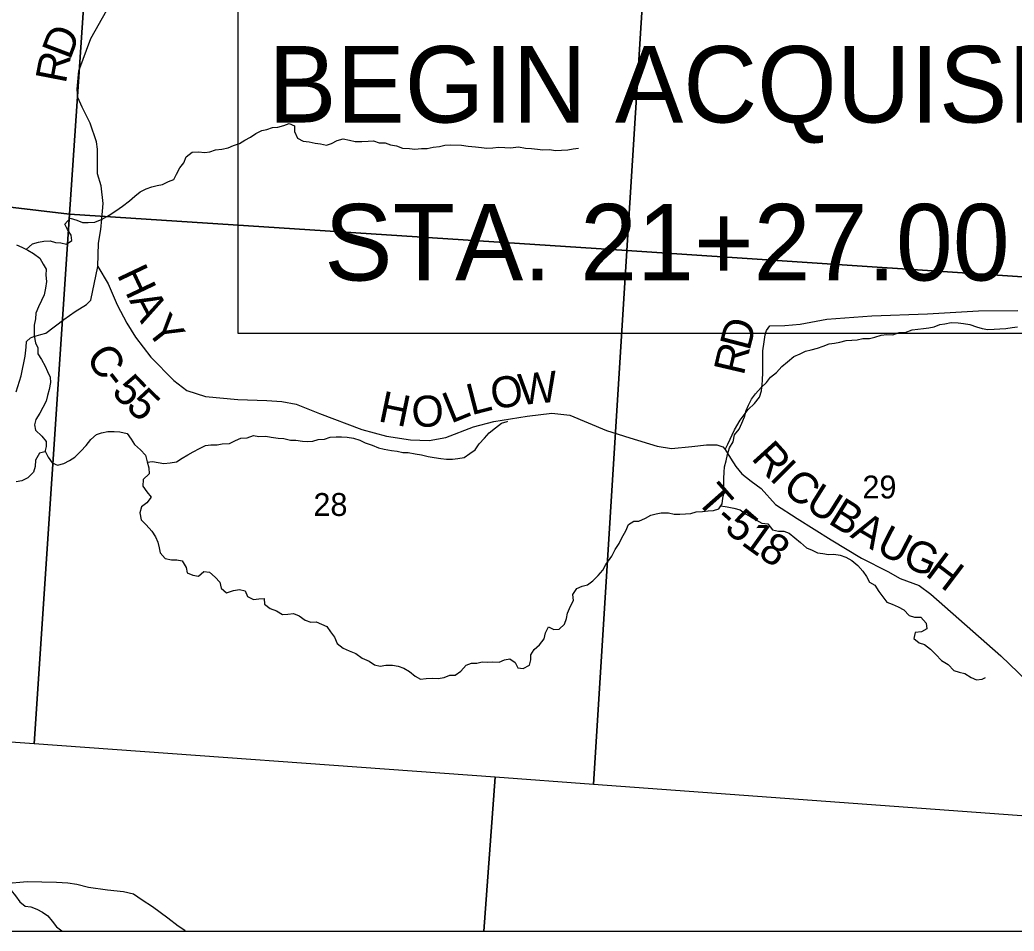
# Model space of a CAD drawing. Extents: x 5.6 to 39.6, y 0.7 to 22.7.
# Drawn here: x 11.039 to 12.858, y 14.907 to 16.574 of the extents above; entities that cross this region are included whole.
import ezdxf

# ---------------------------------------------------------------- set-up
doc = ezdxf.new("R2010")
doc.units = 0
doc.layers.add('Default', color=7, linetype='Continuous')
doc.layers.add('SH_Data', color=7, linetype='Continuous')

msp = doc.modelspace()

# ---------------------------------------------------------------- linework, layer by layer
at = {"layer": 'Default'}
for p, q in [((10.8627, 14.9074), (11.8881, 14.9074)), ((11.8881, 14.9074), (12.9445, 14.9074))]:
    msp.add_line(p, q, dxfattribs=at)
for points in [[(8.2518, 18.5322), (8.2518, 14.9074), (15.0518, 14.9074), (15.0518, 18.0251)], [(8.2518, 18.5322), (8.2518, 14.9074), (15.0518, 14.9074), (15.0518, 18.0251)], [(8.2518, 18.5322), (8.2518, 14.9074), (15.0518, 14.9074), (15.0518, 18.0251)], [(11.1813, 16.1232), (11.1813, 16.1232), (11.1827, 16.1657), (11.187, 16.1911), (11.189, 16.2105), (11.1914, 16.2382), (11.1875, 16.2708), (11.1812, 16.2925), (11.1812, 16.3073), (11.1807, 16.3377), (11.1792, 16.351), (11.1673, 16.3856), (11.1527, 16.4149), (11.1449, 16.4324), (11.1438, 16.4476), (11.147, 16.4813), (11.169, 16.5404), (11.2275, 16.6448)], [(11.0505, 16.1544), (11.0618, 16.1649), (11.0732, 16.1677), (11.0827, 16.1693), (11.0941, 16.1699), (11.1039, 16.1674), (11.1141, 16.1664), (11.1242, 16.1643), (11.1339, 16.1705), (11.1326, 16.1808), (11.126, 16.1911), (11.1213, 16.2007), (11.131, 16.2119), (11.1434, 16.2078), (11.1535, 16.2038), (11.1641, 16.2036), (11.1759, 16.2044), (11.1893, 16.2095), (11.2023, 16.2171), (11.2146, 16.2252), (11.2265, 16.2333), (11.2393, 16.2432), (11.2493, 16.2517), (11.2589, 16.2595), (11.2701, 16.2653), (11.2807, 16.2689), (11.2903, 16.2713), (11.2998, 16.2734), (11.3109, 16.2784), (11.3204, 16.2824), (11.3256, 16.2922), (11.3315, 16.3034), (11.3389, 16.3131), (11.3433, 16.3236), (11.3541, 16.3321), (11.3655, 16.333), (11.3772, 16.332), (11.3867, 16.3329), (11.397, 16.3365), (11.4084, 16.3381), (11.4198, 16.3401), (11.4301, 16.3444), (11.4408, 16.348), (11.4504, 16.3542), (11.4612, 16.3597), (11.4708, 16.3667), (11.4815, 16.3721), (11.491, 16.3738), (11.5009, 16.3774), (11.5112, 16.3783), (11.5222, 16.3811), (11.5318, 16.385), (11.5415, 16.3807), (11.5417, 16.3704), (11.5467, 16.3582), (11.5572, 16.3522), (11.5685, 16.3512), (11.5791, 16.3487), (11.5889, 16.3474), (11.5998, 16.3452), (11.6094, 16.3484), (11.6193, 16.3539), (11.6308, 16.3567), (11.6424, 16.3541), (11.6526, 16.3516), (11.6647, 16.3521), (11.6761, 16.3526), (11.6863, 16.3532), (11.6961, 16.3495), (11.7071, 16.3493), (11.7172, 16.3457), (11.7282, 16.3439), (11.7391, 16.3399), (11.7516, 16.3392), (11.7614, 16.3378), (11.7739, 16.3391), (11.7841, 16.3389), (11.7955, 16.3413), (11.8069, 16.3429), (11.8165, 16.345), (11.8267, 16.3455), (11.8471, 16.345), (11.8592, 16.3436), (11.8724, 16.3418), (11.8834, 16.3408), (11.8936, 16.3398), (11.9042, 16.3404), (11.9145, 16.3413), (11.9266, 16.341), (11.9368, 16.34), (11.9512, 16.3424), (11.9644, 16.3394), (11.975, 16.3392), (11.986, 16.3378), (11.9958, 16.3368), (12.0072, 16.3373), (12.0196, 16.3355), (12.0299, 16.3361), (12.0416, 16.3369), (12.0511, 16.3382), (12.061, 16.3395)], [(11.0329, 16.1629), (11.0427, 16.1585), (11.0532, 16.1529), (11.0636, 16.147), (11.0752, 16.1384), (11.0818, 16.1276), (11.0869, 16.1181), (11.0866, 16.1071), (11.0875, 16.096), (11.0857, 16.0836), (11.0835, 16.0715), (11.0788, 16.061), (11.0728, 16.0497), (11.068, 16.0381), (11.0678, 16.0274), (11.0649, 16.0158), (11.065, 16.0059), (11.0648, 15.9964), (11.0676, 15.9838), (11.0715, 15.9743), (11.0717, 15.9636), (11.0782, 15.9529), (11.0852, 15.941), (11.0895, 15.931), (11.0946, 15.921), (11.0951, 15.9108), (11.0925, 15.8983), (11.0896, 15.887), (11.0868, 15.8768), (11.0812, 15.8652), (11.0753, 15.8547), (11.0682, 15.8435), (11.0657, 15.8337), (11.0678, 15.8238), (11.0789, 15.8129), (11.087, 15.8032), (11.0872, 15.7938), (11.0847, 15.784), (11.0748, 15.7815), (11.0677, 15.7688), (11.0667, 15.7574), (11.0638, 15.7469), (11.0537, 15.7368), (11.0426, 15.731), (11.0319, 15.7294)], [(11.0319, 15.8941), (11.0411, 15.9233), (11.0485, 15.9589), (11.0505, 15.9756), (11.0513, 15.9862), (11.0582, 15.993), (11.0646, 15.9949), (11.0775, 15.9986), (11.0867, 16.0012), (11.1194, 16.026), (11.1399, 16.0407), (11.1608, 16.0535), (11.1688, 16.0618), (11.1813, 16.1232)], [(11.1813, 16.1232), (11.2004, 16.0912), (11.2172, 16.0528), (11.2345, 16.0193), (11.2506, 15.9942), (11.2784, 15.9576), (11.3206, 15.9148), (11.3444, 15.8961), (11.3788, 15.8856), (11.4378, 15.88), (11.4908, 15.8778), (11.5185, 15.8765), (11.5446, 15.8714), (11.5873, 15.8541), (11.6647, 15.8248), (11.7101, 15.8131), (11.754, 15.806), (11.7877, 15.8051), (11.8181, 15.8106), (11.8693, 15.83), (11.9065, 15.8397), (11.9675, 15.8496), (12.0126, 15.855), (12.0452, 15.8514), (12.1124, 15.8233), (12.1552, 15.8098), (12.2051, 15.7943), (12.2312, 15.79), (12.2683, 15.794), (12.2952, 15.7969), (12.3145, 15.7967), (12.3251, 15.7931), (12.3296, 15.7883)], [(12.3296, 15.7883), (12.3296, 15.7883), (12.3346, 15.7981), (12.3465, 15.8243), (12.3572, 15.842), (12.3717, 15.8613), (12.3832, 15.8726), (12.3923, 15.8843), (12.3962, 15.8957), (12.3978, 15.9139), (12.3983, 15.9302), (12.3984, 15.9447), (12.3985, 15.9689), (12.4009, 15.9853), (12.4028, 15.9981), (12.4052, 16.0061), (12.4113, 16.0148), (12.4389, 16.0154), (12.4666, 16.0179), (12.5155, 16.0267), (12.5977, 16.0327), (12.6996, 16.0367), (12.7928, 16.0422), (12.8652, 16.0429)], [(11.9161, 15.3995), (11.9256, 15.4034), (11.9355, 15.4055), (11.9452, 15.3988), (11.9499, 15.3888), (11.9598, 15.3879), (11.9716, 15.3937), (11.9741, 15.4035), (11.974, 15.413), (11.9799, 15.4227), (11.9895, 15.4312), (11.9985, 15.442), (12.0006, 15.4533), (12.0061, 15.4638), (12.0159, 15.4594), (12.0258, 15.46), (12.0358, 15.4689), (12.0394, 15.479), (12.0412, 15.4888), (12.0468, 15.5016), (12.0523, 15.5125), (12.051, 15.5231), (12.0581, 15.534), (12.068, 15.5387), (12.0776, 15.5408), (12.0872, 15.5481), (12.0969, 15.5578), (12.1054, 15.5678), (12.1113, 15.5779), (12.1219, 15.5936), (12.1282, 15.6053), (12.1353, 15.6165), (12.1405, 15.627), (12.1479, 15.6397), (12.1524, 15.651), (12.1624, 15.6572), (12.1718, 15.6574), (12.1837, 15.6628), (12.1937, 15.6683), (12.2032, 15.6707), (12.2127, 15.6724), (12.2256, 15.6725), (12.2365, 15.6704), (12.2463, 15.6701), (12.257, 15.671), (12.2664, 15.6716), (12.2767, 15.6744), (12.2881, 15.6749), (12.2984, 15.6762), (12.3079, 15.6771), (12.3178, 15.6796), (12.324, 15.6893), (12.325, 15.6995), (12.3275, 15.7097), (12.3271, 15.723), (12.327, 15.7355), (12.328, 15.7468), (12.3286, 15.7567), (12.3315, 15.7676), (12.334, 15.779), (12.3373, 15.7914), (12.344, 15.8022), (12.3469, 15.8155), (12.3551, 15.8255), (12.3599, 15.8364), (12.3651, 15.8484), (12.368, 15.8597), (12.3724, 15.8695), (12.3779, 15.8804), (12.3853, 15.8901), (12.3954, 15.9016), (12.4051, 15.9109), (12.4122, 15.921), (12.4233, 15.9291), (12.4334, 15.9402), (12.4438, 15.9491), (12.455, 15.9583), (12.4669, 15.9634), (12.4765, 15.9681), (12.4868, 15.9709), (12.4982, 15.9741), (12.5089, 15.9776), (12.5199, 15.9815), (12.5298, 15.9828), (12.5393, 15.9849), (12.5511, 15.9877), (12.5614, 15.9882), (12.5709, 15.9891), (12.5815, 15.9916), (12.5936, 15.9917), (12.6035, 15.9941), (12.615, 15.9973), (12.6256, 15.9985), (12.6362, 15.9983), (12.6477, 16.0026), (12.659, 16.0023), (12.672, 16.0074), (12.6823, 16.0083), (12.6925, 16.0096), (12.7024, 16.0112), (12.7119, 16.0126)], [(12.7119, 16.0126), (12.7222, 16.0169), (12.7317, 16.0182), (12.7431, 16.0206), (12.7556, 16.0203), (12.7658, 16.0189), (12.7775, 16.0168), (12.7892, 16.0131), (12.7997, 16.0095), (12.8103, 16.0081), (12.8216, 16.0086), (12.8319, 16.0091), (12.8429, 16.01), (12.8547, 16.0117), (12.8642, 16.0126)], [(11.272, 15.7653), (11.2816, 15.7667), (11.2918, 15.7646), (11.3023, 15.7628), (11.3141, 15.7641), (11.3255, 15.7661), (11.3359, 15.7727), (11.3463, 15.7785), (11.3562, 15.7844), (11.3677, 15.7902), (11.3788, 15.7956), (11.3883, 15.7969), (11.3997, 15.7967), (11.4092, 15.7987), (11.4225, 15.7996), (11.4332, 15.8047), (11.4435, 15.8094), (11.4549, 15.8099), (11.4663, 15.8138), (11.4762, 15.812), (11.489, 15.8129), (11.4989, 15.8112), (11.5113, 15.8094), (11.5219, 15.8087), (11.534, 15.8058), (11.5438, 15.8056), (11.5559, 15.8038), (11.5657, 15.8032), (11.5752, 15.8034), (11.5847, 15.8066), (11.5965, 15.8075), (11.6068, 15.8107), (11.6178, 15.8119), (11.6276, 15.8113), (11.6378, 15.8111), (11.6492, 15.809), (11.6612, 15.8057), (11.6709, 15.8009), (11.6837, 15.7964), (11.6953, 15.7912), (11.7055, 15.7891), (11.7191, 15.7865), (11.7293, 15.7852), (11.7395, 15.7831), (11.7493, 15.7828), (11.7625, 15.7803), (11.7738, 15.7785), (11.7863, 15.7759), (11.7968, 15.7738), (11.8093, 15.772), (11.8195, 15.7707), (11.8305, 15.7708), (11.8403, 15.7717), (11.8521, 15.7737), (11.8625, 15.7811), (11.8721, 15.7881), (11.8796, 15.7985), (11.8889, 15.8089), (11.8978, 15.819), (11.909, 15.8278), (11.9202, 15.8363), (11.9305, 15.8395), (11.932, 15.8402)], [(11.085, 15.7854), (11.0909, 15.7743), (11.0982, 15.7639), (11.108, 15.7595), (11.1194, 15.7631), (11.1298, 15.7685), (11.1394, 15.7744), (11.1506, 15.7851), (11.1603, 15.7955), (11.1689, 15.8067), (11.1789, 15.816), (11.1885, 15.8192), (11.1999, 15.8216), (11.2116, 15.8213), (11.2218, 15.8207), (11.2354, 15.8178), (11.2427, 15.8074), (11.2486, 15.7978), (11.2597, 15.7876), (11.2686, 15.778), (11.2717, 15.7661), (11.2749, 15.7547), (11.2758, 15.7437), (11.2646, 15.7337), (11.2639, 15.7212), (11.2713, 15.7108), (11.279, 15.7011), (11.2712, 15.6911), (11.2616, 15.6833), (11.2587, 15.6724), (11.2607, 15.6598), (11.2703, 15.6509), (11.2806, 15.6393), (11.2872, 15.6285), (11.2916, 15.6189), (11.294, 15.6086), (11.2957, 15.5991), (11.3045, 15.589), (11.3162, 15.5865), (11.3261, 15.5867), (11.3362, 15.5845), (11.3432, 15.5726), (11.3452, 15.5627), (11.3557, 15.5583), (11.3655, 15.5566), (11.3756, 15.5651), (11.3861, 15.5641), (11.3965, 15.5551), (11.4047, 15.5455), (11.4075, 15.5348), (11.4171, 15.5262), (11.4297, 15.5305), (11.4411, 15.5325), (11.4513, 15.5296), (11.4556, 15.5197), (11.4665, 15.5141), (11.4763, 15.5151), (11.4862, 15.5156), (11.4867, 15.5053), (11.4968, 15.4975), (11.5088, 15.4931), (11.5196, 15.4868), (11.5295, 15.4873), (11.5394, 15.4886), (11.5502, 15.4842), (11.561, 15.476), (11.5712, 15.4724), (11.581, 15.4729), (11.5908, 15.4689), (11.6005, 15.4645), (11.6071, 15.4549), (11.6149, 15.4452), (11.6195, 15.4334), (11.6303, 15.4252), (11.6412, 15.4204), (11.6536, 15.4155), (11.6655, 15.4069), (11.6783, 15.4013), (11.688, 15.3943), (11.6985, 15.3918), (11.7084, 15.3942), (11.7209, 15.3939), (11.7311, 15.3918), (11.7416, 15.3885), (11.7521, 15.3826), (11.7621, 15.3737), (11.7722, 15.3685), (11.7821, 15.3698), (11.7931, 15.3703), (11.8041, 15.3693), (11.8155, 15.3714), (11.8254, 15.3757), (11.8353, 15.3758), (11.8456, 15.3828), (11.8554, 15.394), (11.8653, 15.3976), (11.8751, 15.3973), (11.8847, 15.4002), (11.8945, 15.3996), (11.9043, 15.3997), (11.9161, 15.3995)], [(12.3296, 15.7883), (12.339, 15.7727), (12.3492, 15.7574), (12.3601, 15.7441), (12.3774, 15.7307), (12.3955, 15.717), (12.4215, 15.688), (12.4611, 15.6623), (12.5233, 15.6229), (12.5788, 15.5895), (12.6272, 15.5653), (12.6498, 15.5527), (12.6846, 15.5396), (12.7061, 15.5239), (12.8338, 15.4112), (12.8817, 15.365), (12.9137, 15.3375), (12.9488, 15.3138), (12.9903, 15.2835), (13.0337, 15.2541), (13.085, 15.2181), (13.1166, 15.197), (13.1449, 15.1722)], [(12.3213, 15.6851), (12.3334, 15.6834), (12.3454, 15.6808), (12.3567, 15.6783), (12.3668, 15.6709), (12.3765, 15.6654), (12.387, 15.6594), (12.3967, 15.6539), (12.4077, 15.6525), (12.4161, 15.6413), (12.4271, 15.6392), (12.4369, 15.639), (12.4467, 15.6354), (12.4571, 15.6268), (12.4671, 15.6182), (12.4786, 15.6085), (12.4888, 15.6045), (12.4985, 15.5993), (12.5083, 15.598), (12.5189, 15.5966), (12.5284, 15.5967), (12.5397, 15.595), (12.5506, 15.5917), (12.5614, 15.5854), (12.5722, 15.5764), (12.5814, 15.5656), (12.5881, 15.556), (12.5935, 15.546), (12.6032, 15.5405), (12.6109, 15.5289), (12.6183, 15.5189), (12.6252, 15.5089), (12.6354, 15.5052), (12.6463, 15.5004), (12.6567, 15.4949), (12.666, 15.4845), (12.6762, 15.482), (12.6875, 15.4817), (12.6975, 15.4705), (12.6984, 15.4602), (12.6888, 15.4551), (12.6774, 15.4539), (12.6745, 15.4429), (12.6846, 15.4347), (12.6943, 15.4315), (12.7051, 15.4229), (12.7151, 15.4132), (12.7251, 15.4024), (12.7378, 15.3949), (12.7478, 15.384), (12.7576, 15.3808), (12.7678, 15.3787), (12.7797, 15.3716), (12.7895, 15.3672), (12.7997, 15.3681), (12.8062, 15.3714)], [(11.8881, 14.9074), (11.9086, 15.1889), (11.0648, 15.2501), (10.8842, 15.2625), (10.8627, 14.9074)], [(12.9445, 14.9074), (12.9641, 15.1117), (12.0885, 15.1757), (11.9086, 15.1889), (11.8881, 14.9074)], [(11.3418, 14.9074), (11.3405, 14.9084), (11.3288, 14.9162), (11.3096, 14.9309), (11.2818, 14.9518), (11.2626, 14.9638), (11.2467, 14.9748), (11.2283, 14.9791), (11.1995, 14.9822), (11.1647, 14.9872), (11.1431, 14.9924), (11.1268, 14.9949), (11.1059, 14.9965), (11.0525, 14.9977), (11.0113, 14.9939), (11.0018, 14.9935), (10.9938, 14.995), (10.9727, 15.0018), (10.9716, 15.002)], [(11.0177, 14.9914), (11.0231, 14.9815), (11.0307, 14.9717), (11.0386, 14.9607), (11.0485, 14.9531), (11.0591, 14.9516), (11.0697, 14.9478), (11.0803, 14.9418), (11.0902, 14.9354), (11.0982, 14.9255), (11.1058, 14.9153), (11.1156, 14.9081), (11.1167, 14.9074)]]:
    msp.add_lwpolyline(points, dxfattribs=at)
for points in [[(11.5163, 17.1975), (12.2127, 17.1504), (12.1494, 16.1525), (11.1299, 16.2192), (11.1778, 16.9289)], [(12.2127, 17.1504), (13.1788, 17.0823), (13.1121, 16.0885), (12.1494, 16.1525)], [(11.1778, 16.9289), (11.1299, 16.2192), (10.5154, 16.2914), (10.5184, 16.2529), (10.169, 16.28), (10.1768, 16.3696), (10.1925, 16.3816), (10.2261, 16.3983), (10.5161, 16.5272), (10.8674, 16.7406)], [(10.169, 16.28), (10.5184, 16.2529), (10.5154, 16.2914), (11.1299, 16.2192), (11.0648, 15.2501), (10.8842, 15.2625), (10.0852, 15.3096)], [(11.1299, 16.2192), (12.1494, 16.1525), (12.0885, 15.1757), (11.9086, 15.1889), (11.0648, 15.2501)], [(12.1494, 16.1525), (13.1121, 16.0885), (13.0667, 15.1046), (12.9641, 15.1117), (12.0885, 15.1757)]]:
    msp.add_lwpolyline(points, close=True, dxfattribs=at)
at = {"layer": 'SH_Data'}
msp.add_lwpolyline([(11.4381, 16.6256), (13.5787, 16.6256), (13.5787, 16.0006), (11.4381, 16.0006)], close=True, dxfattribs=at)

# ---------------------------------------------------------------- texts
at = {"layer": 'Default'}
for s, height, rotation, p in [('D', 0.0568, 69.0875, (11.1308, 16.4996)), ('R', 0.0568, 79.0123, (11.1227, 16.4563)), ('H', 0.0568, 295.3822, (11.2158, 16.1088)), ('A', 0.0568, 297.9251, (11.2384, 16.0612)), ('Y', 0.0568, 308.1886, (11.2679, 16.0077)), ('D', 0.0568, 75.4027, (12.3739, 15.9673)), ('C', 0.0568, 305, (11.1578, 15.9564)), ('R', 0.0568, 76.8413, (12.3633, 15.9222)), ('-', 0.0568, 307.8358, (11.1864, 15.9157)), ('5', 0.0568, 313.843, (11.2049, 15.8924)), ('O', 0.0568, 9.6072, (11.9051, 15.8612)), ('W', 0.0568, 5.4226, (11.9533, 15.8694)), ('5', 0.0568, 316.1292, (11.2309, 15.8654)), ('L', 0.0568, 14.4042, (11.8651, 15.8509)), ('H', 0.0568, 348.3021, (11.6928, 15.8405)), ('O', 0.0568, 2.0608, (11.7565, 15.8291)), ('L', 0.0568, 22.2084, (11.8277, 15.8354)), ('R', 0.0568, 312.2501, (12.3756, 15.7717)), ('I', 0.0568, 314.9528, (12.409, 15.735)), ('C', 0.0568, 322.3668, (12.4315, 15.7132)), ('29', 0.04182, 0, (12.5807, 15.6989)), ('T', 0.0568, 311.5617, (12.2744, 15.6951)), ('U', 0.0568, 327.9155, (12.4734, 15.6813)), ('28', 0.04182, 0, (11.5761, 15.6669)), ('B', 0.0568, 327.9566, (12.5158, 15.6547)), ('-', 0.0568, 318.3148, (12.3078, 15.6582)), ('5', 0.0568, 319.174, (12.3259, 15.642)), ('A', 0.0568, 329.3355, (12.5566, 15.6292)), ('1', 0.0568, 324.4728, (12.3569, 15.6156)), ('U', 0.0568, 332.8427, (12.603, 15.6018)), ('8', 0.0568, 326.721, (12.3874, 15.5939)), ('G', 0.0568, 336.2953, (12.6508, 15.5774)), ('H', 0.0568, 322.8605, (12.6936, 15.5591))]:
    msp.add_text(s, height=height, rotation=rotation, dxfattribs=at).set_placement(p)
at = {"layer": 'SH_Data'}
for s, p in [('BEGIN ACQUISITION', (11.4934, 16.3866)), ('STA. 21+27.00', (11.596, 16.0976))]:
    msp.add_text(s, height=0.14, dxfattribs=at).set_placement(p)

doc.saveas('drawing.dxf')
